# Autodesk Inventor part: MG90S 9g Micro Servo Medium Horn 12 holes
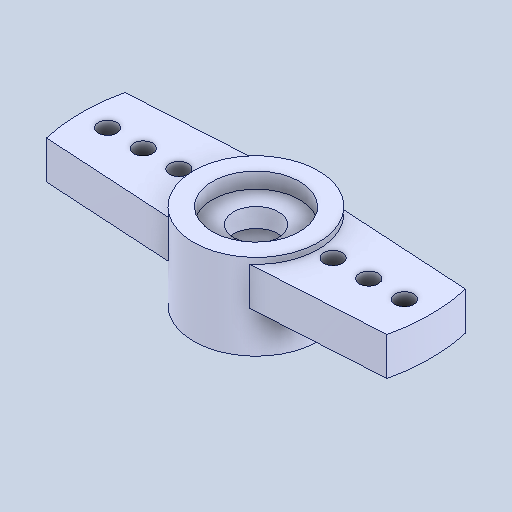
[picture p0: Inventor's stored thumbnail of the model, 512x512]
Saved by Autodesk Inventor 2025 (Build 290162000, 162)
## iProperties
Created: 2025-02
Part Number: MG90S 9g Micro Servo Medium Horn 12 holes
Material: Generico
Description: STEP AP214
Document SubType Name: Modeling
Designer: Ryzen5700u
Density: 1 g/cm^3
Appearance: Default
Author: Ryzen5700u
Revision Number: ANY
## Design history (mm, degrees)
feature "Solido1"
node "Solido2"
